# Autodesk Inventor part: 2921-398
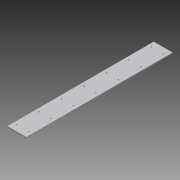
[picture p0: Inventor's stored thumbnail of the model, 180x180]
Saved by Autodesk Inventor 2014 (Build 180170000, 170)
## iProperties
Company: NHTSA/VRTC
Created: 2012-08
Part Number: 2921-398
Material: Acetal Resin, White
Document SubType Name: Modeling
Designer: Mike Vanvoorhis
Density: 1.06 g/cm^3
Mass: 533.604 g
Surface Area: 1729.06 cm^2
Volume: 503.4 cm^3
Project: CHILD SIDE IMPACT SLED
Description: ANTI-REBOUND SLIDER PLATE
Appearance: Smooth - White
Author: Dave Walker
Title: Anti-Rebound Slider Plate
Subject: Child side Impact sled
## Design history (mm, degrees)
sketch "Sketch1"
  geometry: L1 (0, 0)-(101.6, 0); L2 (101.6, 0)-(101.6, 6.35); L3 (101.6, 6.35)-(0, 6.35); L4 (0, 6.35)-(0, 0)
  constraints: 8 end point, 2 parallel, 1 horizontal, 1 perpendicular
  dimensions: "d0" = 101.6 distance of L3.end L2.end; "d1" = 6.35 distance of L2.end L1.end
extrude "Extrusion1" new body sketch "Sketch1" distance "d2" = 787.4; taper "d3" = 0 deg
sketch "Sketch2"
  geometry: L1 (101.6, 0)-(101.6, -787.4) reference; L2 (19.05, -31.75)-(19.05, -152.4); L3 (19.05, -152.4)-(19.05, -273.05); L4 (19.05, -273.05)-(19.05, -393.7); L5 (19.05, -393.7)-(19.05, -514.35); L6 (19.05, -514.35)-(19.05, -635); L7 (19.05, -635)-(19.05, -755.65); L8 (19.05, -755.65)-(82.55, -755.65); L9 (82.55, -755.65)-(82.55, -635); L10 (82.55, -635)-(82.55, -514.35); L11 (82.55, -514.35)-(82.55, -393.7); L12 (82.55, -393.7)-(82.55, -273.05); L13 (82.55, -273.05)-(82.55, -152.4); L14 (82.55, -152.4)-(82.55, -31.75)
  constraints: 26 end point, 6 parallel, 5 collinear
  dimensions: "d5" = 120.65 distance of L2.start L2.end; "d6" = 120.65 distance of L2.end L3.end; "d7" = 120.65 distance of L3.end L4.end; "d8" = 120.65 distance of L4.end L5.end; "d9" = 120.65 distance of L5.end L6.end; "d10" = 120.65 distance of L6.end L7.end; "d11" = 63.5 distance of L7.end L8.end; "d12" = 120.65 distance of L8.end L9.end; "d13" = 120.65 distance of L9.end L10.end; "d14" = 120.65 distance of L10.end L11.end; "d15" = 120.65 distance of L11.end L12.end; "d16" = 120.65 distance of L12.end L13.end; "d17" = 120.65 distance of L13.end L14.end
hole "Hole1" sketch "Sketch2" at (19.05, -31.75), (19.05, -152.4), (19.05, -273.05), (19.05, -393.7), (19.05, -635), (19.05, -755.65), (82.55, -755.65), (82.55, -635), (82.55, -514.35), (82.55, -393.7), (82.55, -273.05), (82.55, -152.4)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 diameter "d19" = 6.35; stored, may be unused: countersink angle "d23" = 82 deg, drill point angle "d25" = 118 deg; dims "d20" = 19.05, "d21" = 10.414, "d22" = 3.175, "d24" = 25.4
sketch "Sketch3"
  geometry: L1 (0, 0)-(0, -787.4) reference; L2 (19.05, -393.7)-(19.05, -514.35); C1 r 5.207 at (19.05, -393.7) reference
  constraints: 2 end point, 1 parallel
  dimensions: "d26" = 120.65 distance of L2.start L2.end
hole "Hole2" sketch "Sketch3" at (19.05, -514.35) diameter "d27" = 6.35; stored, may be unused: countersink angle "d31" = 82 deg, drill point angle "d33" = 118 deg; dims "d28" = 19.05, "d29" = 10.414, "d30" = 3.175, "d32" = 25.4
chamfer "Chamfer1" distance "d34" = 6.35; stored, may be unused: second distance "d35" = 3.175, angle "d36" = 45 deg
body "Solid1"
